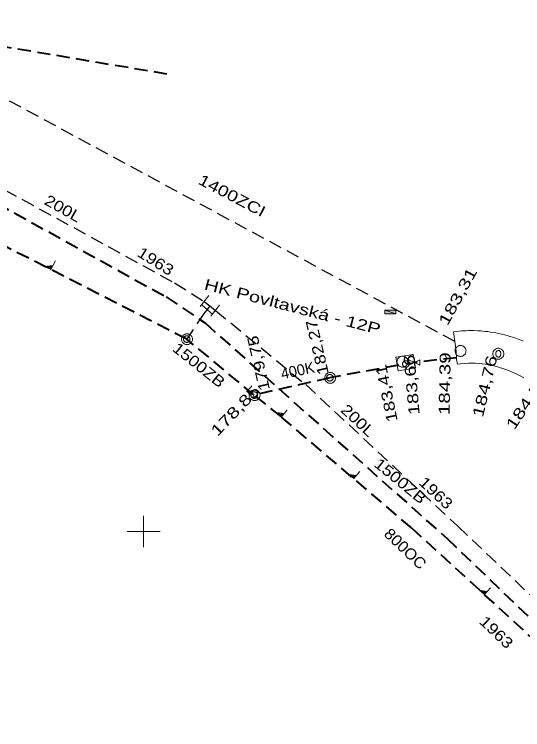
# Model space of a CAD drawing. Extents: x -740851 to -738888, y -1041382 to -1040235.
# Drawn here: x -739761.8 to -739715.4, y -1040568.1 to -1040502.8 of the extents above; entities that cross this region are included whole.
import ezdxf

# ---------------------------------------------------------------- set-up
doc = ezdxf.new("R2010")
doc.units = 0
doc.header["$LTSCALE"] = 0.4
doc.linetypes.add('MEDIUM_DASHED', pattern=[4.5, 3, -1.5])
for name, color, linetype, lineweight in [('1', 7, 'Continuous', 13), ('18', 7, 'Continuous', 13), ('20', 7, 'MEDIUM_DASHED', 25), ('8', 7, 'Continuous', 13)]:
    doc.layers.add(name, color=color, linetype=linetype, lineweight=lineweight)

msp = doc.modelspace()

# ---------------------------------------------------------------- hatches: boundary and pattern name
at = {"layer": '18'}
msp.add_hatch(color=256, dxfattribs=at).paths.add_polyline_path([(-739727.98, -1040529.82), (-739727.98, -1040530.16), (-739726.98, -1040530.16), (-739726.98, -1040529.82)])

# ---------------------------------------------------------------- linework, layer by layer
at = {"layer": '1'}
for p, q in [((-739750, -1040548.571), (-739750, -1040551.429)), ((-739751.48, -1040550), (-739748.48, -1040550))]:
    msp.add_line(p, q, dxfattribs=at)
at = {"layer": '18', "linetype": 'MEDIUM_DASHED', "lineweight": 40}
for p, q in [((-739746.06, -1040532.45), (-739799.87, -1040504.96)), ((-739739.89, -1040537.56), (-739746.06, -1040532.45)), ((-739721.427, -1040534.154), (-739725.27, -1040534.59)), ((-739726.71, -1040534.83), (-739732.99, -1040535.98)), ((-739732.99, -1040535.98), (-739739.89, -1040537.56))]:
    msp.add_line(p, q, dxfattribs=at)
at = {"layer": '18', "linetype": 'MEDIUM_DASHED', "lineweight": 25}
msp.add_line((-739721.586, -1040532.672), (-739764.8, -1040509.34), dxfattribs=at)
at = {"layer": '18'}
for p, q in [((-739727.98, -1040529.82), (-739726.98, -1040530.16)), ((-739725.27, -1040534.59), (-739725.27, -1040534.26)), ((-739725.27, -1040534.59), (-739725.27, -1040534.87))]:
    msp.add_line(p, q, dxfattribs=at)
for points in [[(-739758.045, -1040525.295), (-739758.462, -1040526.112), (-739759.045, -1040525.814), (-739758.274, -1040525.743)], [(-739758.358, -1040525.803), (-739758.48, -1040526.041), (-739758.852, -1040525.851), (-739758.354, -1040525.805)], [(-739758.445, -1040525.867), (-739758.506, -1040525.986), (-739758.697, -1040525.889), (-739758.441, -1040525.869)], [(-739715.285, -1040535.999), (-739715.498, -1040535.875), (-739715.748, -1040535.737), (-739715.932, -1040535.643), (-739716.251, -1040535.491), (-739716.649, -1040535.321), (-739717.184, -1040535.126), (-739717.9, -1040534.921), (-739718.298, -1040534.833), (-739718.809, -1040534.746), (-739719.084, -1040534.712), (-739719.344, -1040534.687), (-739719.721, -1040534.664), (-739720.34, -1040534.658), (-739720.728, -1040534.676), (-739721.074, -1040534.706), (-739721.326, -1040534.735), (-739721.414, -1040534.316), (-739721.473, -1040533.565), (-739721.698, -1040531.779), (-739721.404, -1040531.744), (-739721.17, -1040531.721), (-739720.972, -1040531.706), (-739720.749, -1040531.692), (-739720.551, -1040531.683), (-739720.33, -1040531.677), (-739720.12, -1040531.676), (-739719.857, -1040531.678), (-739719.512, -1040531.69), (-739719.428, -1040531.694), (-739719.22, -1040531.707), (-739719.041, -1040531.722), (-739718.772, -1040531.748), (-739718.563, -1040531.773), (-739718.324, -1040531.805), (-739718.056, -1040531.848), (-739717.844, -1040531.885), (-739717.59, -1040531.936), (-739717.32, -1040531.995), (-739717.187, -1040532.027), (-739717.044, -1040532.063), (-739716.794, -1040532.13), (-739716.549, -1040532.201), (-739716.415, -1040532.243), (-739716, -1040532.381), (-739715.564, -1040532.545), (-739715.354, -1040532.631)], [(-739736.875, -1040538.899), (-739737.419, -1040539.537), (-739737.875, -1040539.149), (-739737.174, -1040539.249)], [(-739737.262, -1040539.285), (-739737.42, -1040539.471), (-739737.711, -1040539.223), (-739737.259, -1040539.287)], [(-739737.352, -1040539.323), (-739737.432, -1040539.416), (-739737.581, -1040539.289), (-739737.349, -1040539.326)], [(-739730.249, -1040544.549), (-739730.793, -1040545.187), (-739731.249, -1040544.799), (-739730.547, -1040544.899)], [(-739730.635, -1040544.935), (-739730.794, -1040545.12), (-739731.085, -1040544.872), (-739730.632, -1040544.937)], [(-739730.726, -1040544.973), (-739730.805, -1040545.066), (-739730.955, -1040544.939), (-739730.723, -1040544.976)], [(-739718.317, -1040555.147), (-739718.879, -1040555.761), (-739719.317, -1040555.36), (-739718.626, -1040555.484)], [(-739718.714, -1040555.516), (-739718.878, -1040555.695), (-739719.158, -1040555.439), (-739718.711, -1040555.519)], [(-739718.806, -1040555.551), (-739718.887, -1040555.641), (-739719.031, -1040555.509), (-739718.803, -1040555.554)]]:
    msp.add_lwpolyline(points, dxfattribs=at)
for points in [[(-739727.98, -1040529.82), (-739727.98, -1040530.16), (-739726.98, -1040530.16), (-739726.98, -1040529.82)], [(-739745.53, -1040532.46), (-739745.54, -1040532.41), (-739745.54, -1040532.36), (-739745.56, -1040532.31), (-739745.58, -1040532.26), (-739745.6, -1040532.21), (-739745.63, -1040532.17), (-739745.66, -1040532.13), (-739745.7, -1040532.09), (-739745.74, -1040532.06), (-739745.78, -1040532.03), (-739745.83, -1040532.01), (-739745.88, -1040531.99), (-739745.93, -1040531.97), (-739745.98, -1040531.97), (-739746.03, -1040531.96), (-739746.08, -1040531.97), (-739746.13, -1040531.97), (-739746.18, -1040531.99), (-739746.23, -1040532.01), (-739746.28, -1040532.03), (-739746.32, -1040532.06), (-739746.36, -1040532.09), (-739746.4, -1040532.13), (-739746.43, -1040532.17), (-739746.46, -1040532.21), (-739746.48, -1040532.26), (-739746.5, -1040532.31), (-739746.52, -1040532.36), (-739746.52, -1040532.41), (-739746.53, -1040532.46), (-739746.52, -1040532.51), (-739746.52, -1040532.56), (-739746.5, -1040532.61), (-739746.48, -1040532.66), (-739746.46, -1040532.71), (-739746.43, -1040532.75), (-739746.4, -1040532.79), (-739746.36, -1040532.83), (-739746.32, -1040532.86), (-739746.28, -1040532.89), (-739746.23, -1040532.91), (-739746.18, -1040532.93), (-739746.13, -1040532.95), (-739746.08, -1040532.95), (-739746.03, -1040532.96), (-739745.98, -1040532.95), (-739745.93, -1040532.95), (-739745.88, -1040532.93), (-739745.83, -1040532.91), (-739745.78, -1040532.89), (-739745.74, -1040532.86), (-739745.7, -1040532.83), (-739745.66, -1040532.79), (-739745.63, -1040532.75), (-739745.6, -1040532.71), (-739745.58, -1040532.66), (-739745.56, -1040532.61), (-739745.54, -1040532.56), (-739745.54, -1040532.51)], [(-739745.76, -1040532.45), (-739745.76, -1040532.42), (-739745.766, -1040532.39), (-739745.772, -1040532.36), (-739745.784, -1040532.33), (-739745.802, -1040532.3), (-739745.82, -1040532.276), (-739745.838, -1040532.252), (-739745.862, -1040532.228), (-739745.886, -1040532.21), (-739745.91, -1040532.192), (-739745.94, -1040532.174), (-739745.97, -1040532.162), (-739746, -1040532.156), (-739746.03, -1040532.15), (-739746.06, -1040532.15), (-739746.09, -1040532.15), (-739746.12, -1040532.156), (-739746.15, -1040532.162), (-739746.18, -1040532.174), (-739746.21, -1040532.192), (-739746.234, -1040532.21), (-739746.258, -1040532.228), (-739746.282, -1040532.252), (-739746.3, -1040532.276), (-739746.318, -1040532.3), (-739746.336, -1040532.33), (-739746.348, -1040532.36), (-739746.354, -1040532.39), (-739746.36, -1040532.42), (-739746.36, -1040532.45), (-739746.36, -1040532.48), (-739746.354, -1040532.51), (-739746.348, -1040532.54), (-739746.336, -1040532.57), (-739746.318, -1040532.6), (-739746.3, -1040532.624), (-739746.282, -1040532.648), (-739746.258, -1040532.672), (-739746.234, -1040532.69), (-739746.21, -1040532.708), (-739746.18, -1040532.726), (-739746.15, -1040532.738), (-739746.12, -1040532.744), (-739746.09, -1040532.75), (-739746.06, -1040532.75), (-739746.03, -1040532.75), (-739746, -1040532.744), (-739745.97, -1040532.738), (-739745.94, -1040532.726), (-739745.91, -1040532.708), (-739745.886, -1040532.69), (-739745.862, -1040532.672), (-739745.838, -1040532.648), (-739745.82, -1040532.624), (-739745.802, -1040532.6), (-739745.784, -1040532.57), (-739745.772, -1040532.54), (-739745.766, -1040532.51), (-739745.76, -1040532.48)], [(-739720.617, -1040533.774), (-739720.601, -1040533.725), (-739720.577, -1040533.681), (-739720.571, -1040533.628), (-739720.564, -1040533.574), (-739720.558, -1040533.52), (-739720.565, -1040533.47), (-739720.572, -1040533.421), (-739720.588, -1040533.366), (-739720.609, -1040533.32), (-739720.629, -1040533.274), (-739720.664, -1040533.233), (-739720.698, -1040533.191), (-739720.733, -1040533.149), (-739720.777, -1040533.125), (-739720.816, -1040533.092), (-739720.865, -1040533.077), (-739720.909, -1040533.052), (-739720.963, -1040533.046), (-739721.017, -1040533.039), (-739721.07, -1040533.033), (-739721.12, -1040533.04), (-739721.17, -1040533.047), (-739721.225, -1040533.063), (-739721.27, -1040533.084), (-739721.316, -1040533.105), (-739721.358, -1040533.139), (-739721.4, -1040533.174), (-739721.442, -1040533.208), (-739721.466, -1040533.252), (-739721.499, -1040533.291), (-739721.514, -1040533.34), (-739721.538, -1040533.384), (-739721.545, -1040533.438), (-739721.551, -1040533.492), (-739721.558, -1040533.546), (-739721.551, -1040533.595), (-739721.543, -1040533.645), (-739721.527, -1040533.7), (-739721.507, -1040533.746), (-739721.486, -1040533.791), (-739721.451, -1040533.833), (-739721.417, -1040533.875), (-739721.383, -1040533.917), (-739721.338, -1040533.941), (-739721.299, -1040533.974), (-739721.25, -1040533.989), (-739721.206, -1040534.013), (-739721.152, -1040534.02), (-739721.099, -1040534.026), (-739721.045, -1040534.033), (-739720.995, -1040534.026), (-739720.945, -1040534.019), (-739720.891, -1040534.003), (-739720.845, -1040533.982), (-739720.799, -1040533.961), (-739720.757, -1040533.927), (-739720.716, -1040533.892), (-739720.674, -1040533.858), (-739720.65, -1040533.814)], [(-739726.97, -1040534.11), (-739725.38, -1040533.85), (-739725.17, -1040535.07), (-739726.76, -1040535.34)], [(-739717.107, -1040533.795), (-739717.107, -1040533.745), (-739717.117, -1040533.695), (-739717.127, -1040533.645), (-739717.147, -1040533.595), (-739717.177, -1040533.545), (-739717.207, -1040533.505), (-739717.237, -1040533.465), (-739717.277, -1040533.425), (-739717.317, -1040533.395), (-739717.357, -1040533.365), (-739717.407, -1040533.335), (-739717.457, -1040533.315), (-739717.507, -1040533.305), (-739717.557, -1040533.295), (-739717.607, -1040533.295), (-739717.657, -1040533.295), (-739717.707, -1040533.305), (-739717.757, -1040533.315), (-739717.807, -1040533.335), (-739717.857, -1040533.365), (-739717.897, -1040533.395), (-739717.937, -1040533.425), (-739717.977, -1040533.465), (-739718.007, -1040533.505), (-739718.037, -1040533.545), (-739718.067, -1040533.595), (-739718.087, -1040533.645), (-739718.097, -1040533.695), (-739718.107, -1040533.745), (-739718.107, -1040533.795), (-739718.107, -1040533.845), (-739718.097, -1040533.895), (-739718.087, -1040533.945), (-739718.067, -1040533.995), (-739718.037, -1040534.045), (-739718.007, -1040534.085), (-739717.977, -1040534.125), (-739717.937, -1040534.165), (-739717.897, -1040534.195), (-739717.857, -1040534.225), (-739717.807, -1040534.255), (-739717.757, -1040534.275), (-739717.707, -1040534.285), (-739717.657, -1040534.295), (-739717.607, -1040534.295), (-739717.557, -1040534.295), (-739717.507, -1040534.285), (-739717.457, -1040534.275), (-739717.407, -1040534.255), (-739717.357, -1040534.225), (-739717.317, -1040534.195), (-739717.277, -1040534.165), (-739717.237, -1040534.125), (-739717.207, -1040534.085), (-739717.177, -1040534.045), (-739717.147, -1040533.995), (-739717.127, -1040533.945), (-739717.117, -1040533.895), (-739717.107, -1040533.845)], [(-739717.667, -1040533.485), (-739717.727, -1040533.515), (-739717.787, -1040533.575), (-739717.817, -1040533.625), (-739717.847, -1040533.715), (-739717.847, -1040533.875), (-739717.817, -1040533.965), (-739717.787, -1040534.015), (-739717.727, -1040534.075), (-739717.667, -1040534.105), (-739717.547, -1040534.105), (-739717.487, -1040534.075), (-739717.427, -1040534.015), (-739717.397, -1040533.965), (-739717.367, -1040533.875), (-739717.367, -1040533.715), (-739717.397, -1040533.625), (-739717.427, -1040533.575), (-739717.487, -1040533.515), (-739717.547, -1040533.485)], [(-739725.86, -1040534.51), (-739725.87, -1040534.46), (-739725.87, -1040534.41), (-739725.89, -1040534.36), (-739725.91, -1040534.31), (-739725.93, -1040534.26), (-739725.96, -1040534.22), (-739725.99, -1040534.18), (-739726.03, -1040534.14), (-739726.07, -1040534.11), (-739726.11, -1040534.08), (-739726.16, -1040534.06), (-739726.21, -1040534.04), (-739726.26, -1040534.02), (-739726.31, -1040534.02), (-739726.36, -1040534.01), (-739726.41, -1040534.02), (-739726.46, -1040534.02), (-739726.51, -1040534.04), (-739726.56, -1040534.06), (-739726.61, -1040534.08), (-739726.65, -1040534.11), (-739726.69, -1040534.14), (-739726.73, -1040534.18), (-739726.76, -1040534.22), (-739726.79, -1040534.26), (-739726.81, -1040534.31), (-739726.83, -1040534.36), (-739726.85, -1040534.41), (-739726.85, -1040534.46), (-739726.86, -1040534.51), (-739726.85, -1040534.56), (-739726.85, -1040534.61), (-739726.83, -1040534.66), (-739726.81, -1040534.71), (-739726.79, -1040534.76), (-739726.76, -1040534.8), (-739726.73, -1040534.84), (-739726.69, -1040534.88), (-739726.65, -1040534.91), (-739726.61, -1040534.94), (-739726.56, -1040534.96), (-739726.51, -1040534.98), (-739726.46, -1040535), (-739726.41, -1040535), (-739726.36, -1040535.01), (-739726.31, -1040535), (-739726.26, -1040535), (-739726.21, -1040534.98), (-739726.16, -1040534.96), (-739726.11, -1040534.94), (-739726.07, -1040534.91), (-739726.03, -1040534.88), (-739725.99, -1040534.84), (-739725.96, -1040534.8), (-739725.93, -1040534.76), (-739725.91, -1040534.71), (-739725.89, -1040534.66), (-739725.87, -1040534.61), (-739725.87, -1040534.56)], [(-739725.754, -1040534.721), (-739725.754, -1040534.691), (-739725.76, -1040534.661), (-739725.766, -1040534.631), (-739725.778, -1040534.601), (-739725.796, -1040534.571), (-739725.814, -1040534.547), (-739725.832, -1040534.523), (-739725.856, -1040534.499), (-739725.88, -1040534.481), (-739725.904, -1040534.463), (-739725.934, -1040534.445), (-739725.964, -1040534.433), (-739725.994, -1040534.427), (-739726.024, -1040534.421), (-739726.054, -1040534.421), (-739726.084, -1040534.421), (-739726.114, -1040534.427), (-739726.144, -1040534.433), (-739726.174, -1040534.445), (-739726.204, -1040534.463), (-739726.228, -1040534.481), (-739726.252, -1040534.499), (-739726.276, -1040534.523), (-739726.294, -1040534.547), (-739726.312, -1040534.571), (-739726.33, -1040534.601), (-739726.342, -1040534.631), (-739726.348, -1040534.661), (-739726.354, -1040534.691), (-739726.354, -1040534.721), (-739726.354, -1040534.751), (-739726.348, -1040534.781), (-739726.342, -1040534.811), (-739726.33, -1040534.841), (-739726.312, -1040534.871), (-739726.294, -1040534.895), (-739726.276, -1040534.919), (-739726.252, -1040534.943), (-739726.228, -1040534.961), (-739726.204, -1040534.979), (-739726.174, -1040534.997), (-739726.144, -1040535.009), (-739726.114, -1040535.015), (-739726.084, -1040535.021), (-739726.054, -1040535.021), (-739726.024, -1040535.021), (-739725.994, -1040535.015), (-739725.964, -1040535.009), (-739725.934, -1040534.997), (-739725.904, -1040534.979), (-739725.88, -1040534.961), (-739725.856, -1040534.943), (-739725.832, -1040534.919), (-739725.814, -1040534.895), (-739725.796, -1040534.871), (-739725.778, -1040534.841), (-739725.766, -1040534.811), (-739725.76, -1040534.781), (-739725.754, -1040534.751)], [(-739725.77, -1040534.34), (-739724.77, -1040534.84), (-739724.77, -1040534.34), (-739725.77, -1040534.84)], [(-739732.46, -1040535.99), (-739732.47, -1040535.94), (-739732.47, -1040535.89), (-739732.49, -1040535.84), (-739732.51, -1040535.79), (-739732.53, -1040535.74), (-739732.56, -1040535.7), (-739732.59, -1040535.66), (-739732.63, -1040535.62), (-739732.67, -1040535.59), (-739732.71, -1040535.56), (-739732.76, -1040535.54), (-739732.81, -1040535.52), (-739732.86, -1040535.5), (-739732.91, -1040535.5), (-739732.96, -1040535.49), (-739733.01, -1040535.5), (-739733.06, -1040535.5), (-739733.11, -1040535.52), (-739733.16, -1040535.54), (-739733.21, -1040535.56), (-739733.25, -1040535.59), (-739733.29, -1040535.62), (-739733.33, -1040535.66), (-739733.36, -1040535.7), (-739733.39, -1040535.74), (-739733.41, -1040535.79), (-739733.43, -1040535.84), (-739733.45, -1040535.89), (-739733.45, -1040535.94), (-739733.46, -1040535.99), (-739733.45, -1040536.04), (-739733.45, -1040536.09), (-739733.43, -1040536.14), (-739733.41, -1040536.19), (-739733.39, -1040536.24), (-739733.36, -1040536.28), (-739733.33, -1040536.32), (-739733.29, -1040536.36), (-739733.25, -1040536.39), (-739733.21, -1040536.42), (-739733.16, -1040536.44), (-739733.11, -1040536.46), (-739733.06, -1040536.48), (-739733.01, -1040536.48), (-739732.96, -1040536.49), (-739732.91, -1040536.48), (-739732.86, -1040536.48), (-739732.81, -1040536.46), (-739732.76, -1040536.44), (-739732.71, -1040536.42), (-739732.67, -1040536.39), (-739732.63, -1040536.36), (-739732.59, -1040536.32), (-739732.56, -1040536.28), (-739732.53, -1040536.24), (-739732.51, -1040536.19), (-739732.49, -1040536.14), (-739732.47, -1040536.09), (-739732.47, -1040536.04)], [(-739732.69, -1040535.98), (-739732.69, -1040535.95), (-739732.696, -1040535.92), (-739732.702, -1040535.89), (-739732.714, -1040535.86), (-739732.732, -1040535.83), (-739732.75, -1040535.806), (-739732.768, -1040535.782), (-739732.792, -1040535.758), (-739732.816, -1040535.74), (-739732.84, -1040535.722), (-739732.87, -1040535.704), (-739732.9, -1040535.692), (-739732.93, -1040535.686), (-739732.96, -1040535.68), (-739732.99, -1040535.68), (-739733.02, -1040535.68), (-739733.05, -1040535.686), (-739733.08, -1040535.692), (-739733.11, -1040535.704), (-739733.14, -1040535.722), (-739733.164, -1040535.74), (-739733.188, -1040535.758), (-739733.212, -1040535.782), (-739733.23, -1040535.806), (-739733.248, -1040535.83), (-739733.266, -1040535.86), (-739733.278, -1040535.89), (-739733.284, -1040535.92), (-739733.29, -1040535.95), (-739733.29, -1040535.98), (-739733.29, -1040536.01), (-739733.284, -1040536.04), (-739733.278, -1040536.07), (-739733.266, -1040536.1), (-739733.248, -1040536.13), (-739733.23, -1040536.154), (-739733.212, -1040536.178), (-739733.188, -1040536.202), (-739733.164, -1040536.22), (-739733.14, -1040536.238), (-739733.11, -1040536.256), (-739733.08, -1040536.268), (-739733.05, -1040536.274), (-739733.02, -1040536.28), (-739732.99, -1040536.28), (-739732.96, -1040536.28), (-739732.93, -1040536.274), (-739732.9, -1040536.268), (-739732.87, -1040536.256), (-739732.84, -1040536.238), (-739732.816, -1040536.22), (-739732.792, -1040536.202), (-739732.768, -1040536.178), (-739732.75, -1040536.154), (-739732.732, -1040536.13), (-739732.714, -1040536.1), (-739732.702, -1040536.07), (-739732.696, -1040536.04), (-739732.69, -1040536.01)], [(-739739.36, -1040537.57), (-739739.37, -1040537.52), (-739739.37, -1040537.47), (-739739.39, -1040537.42), (-739739.41, -1040537.37), (-739739.43, -1040537.32), (-739739.46, -1040537.28), (-739739.49, -1040537.24), (-739739.53, -1040537.2), (-739739.57, -1040537.17), (-739739.61, -1040537.14), (-739739.66, -1040537.12), (-739739.71, -1040537.1), (-739739.76, -1040537.08), (-739739.81, -1040537.08), (-739739.86, -1040537.07), (-739739.91, -1040537.08), (-739739.96, -1040537.08), (-739740.01, -1040537.1), (-739740.06, -1040537.12), (-739740.11, -1040537.14), (-739740.15, -1040537.17), (-739740.19, -1040537.2), (-739740.23, -1040537.24), (-739740.26, -1040537.28), (-739740.29, -1040537.32), (-739740.31, -1040537.37), (-739740.33, -1040537.42), (-739740.35, -1040537.47), (-739740.35, -1040537.52), (-739740.36, -1040537.57), (-739740.35, -1040537.62), (-739740.35, -1040537.67), (-739740.33, -1040537.72), (-739740.31, -1040537.77), (-739740.29, -1040537.82), (-739740.26, -1040537.86), (-739740.23, -1040537.9), (-739740.19, -1040537.94), (-739740.15, -1040537.97), (-739740.11, -1040538), (-739740.06, -1040538.02), (-739740.01, -1040538.04), (-739739.96, -1040538.06), (-739739.91, -1040538.06), (-739739.86, -1040538.07), (-739739.81, -1040538.06), (-739739.76, -1040538.06), (-739739.71, -1040538.04), (-739739.66, -1040538.02), (-739739.61, -1040538), (-739739.57, -1040537.97), (-739739.53, -1040537.94), (-739739.49, -1040537.9), (-739739.46, -1040537.86), (-739739.43, -1040537.82), (-739739.41, -1040537.77), (-739739.39, -1040537.72), (-739739.37, -1040537.67), (-739739.37, -1040537.62)], [(-739739.59, -1040537.56), (-739739.59, -1040537.53), (-739739.596, -1040537.5), (-739739.602, -1040537.47), (-739739.614, -1040537.44), (-739739.632, -1040537.41), (-739739.65, -1040537.386), (-739739.668, -1040537.362), (-739739.692, -1040537.338), (-739739.716, -1040537.32), (-739739.74, -1040537.302), (-739739.77, -1040537.284), (-739739.8, -1040537.272), (-739739.83, -1040537.266), (-739739.86, -1040537.26), (-739739.89, -1040537.26), (-739739.92, -1040537.26), (-739739.95, -1040537.266), (-739739.98, -1040537.272), (-739740.01, -1040537.284), (-739740.04, -1040537.302), (-739740.064, -1040537.32), (-739740.088, -1040537.338), (-739740.112, -1040537.362), (-739740.13, -1040537.386), (-739740.148, -1040537.41), (-739740.166, -1040537.44), (-739740.178, -1040537.47), (-739740.184, -1040537.5), (-739740.19, -1040537.53), (-739740.19, -1040537.56), (-739740.19, -1040537.59), (-739740.184, -1040537.62), (-739740.178, -1040537.65), (-739740.166, -1040537.68), (-739740.148, -1040537.71), (-739740.13, -1040537.734), (-739740.112, -1040537.758), (-739740.088, -1040537.782), (-739740.064, -1040537.8), (-739740.04, -1040537.818), (-739740.01, -1040537.836), (-739739.98, -1040537.848), (-739739.95, -1040537.854), (-739739.92, -1040537.86), (-739739.89, -1040537.86), (-739739.86, -1040537.86), (-739739.83, -1040537.854), (-739739.8, -1040537.848), (-739739.77, -1040537.836), (-739739.74, -1040537.818), (-739739.716, -1040537.8), (-739739.692, -1040537.782), (-739739.668, -1040537.758), (-739739.65, -1040537.734), (-739739.632, -1040537.71), (-739739.614, -1040537.68), (-739739.602, -1040537.65), (-739739.596, -1040537.62), (-739739.59, -1040537.59)]]:
    msp.add_lwpolyline(points, close=True, dxfattribs=at)
at = {"layer": '18', "linetype": 'MEDIUM_DASHED', "lineweight": 40}
msp.add_lwpolyline([(-739713.989, -1040560.24), (-739725.522, -1040549.684), (-739737.438, -1040539.524), (-739739.89, -1040537.56)], dxfattribs=at)
at = {"layer": '20', "lineweight": 40}
msp.add_line((-739747.86, -1040508.27), (-739780.43, -1040502.81), dxfattribs=at)
at = {"layer": '8'}
for p, q in [((-739744.027, -1040528.469), (-739744.829, -1040529.469)), ((-739743.66, -1040530.199), (-739744.66, -1040529.367)), ((-739743.86, -1040530.37), (-739743.064, -1040529.37))]:
    msp.add_line(p, q, dxfattribs=at)
at = {"layer": '8', "lineweight": 25}
msp.add_line((-739743.94, -1040529.424), (-739744.2, -1040529.75), dxfattribs=at)
at = {"layer": '8', "linetype": 'MEDIUM_DASHED', "lineweight": 40}
msp.add_lwpolyline([(-739800.406, -1040510.509), (-739783.874, -1040510.33), (-739769.682, -1040516.575), (-739747.937, -1040528.604), (-739744.345, -1040531.012), (-739722.292, -1040550.654), (-739710.435, -1040562.012), (-739703.68, -1040568.1)], dxfattribs=at)
at = {"layer": '8', "linetype": 'MEDIUM_DASHED', "lineweight": 25}
for points in [[(-739765.844, -1040517.089), (-739747.16, -1040527.33), (-739744.46, -1040529.01)], [(-739744.46, -1040529.01), (-739743.94, -1040529.424), (-739743.43, -1040529.83)], [(-739744.2, -1040529.75), (-739744.468, -1040530.073), (-739746.06, -1040532.45)], [(-739743.43, -1040529.83), (-739735.19, -1040536.61), (-739721.3, -1040549.54), (-739710.4, -1040559.88)]]:
    msp.add_lwpolyline(points, dxfattribs=at)

# ---------------------------------------------------------------- texts
at = {"layer": '18'}
for s, rotation, width, p in [('1400ZCI', 332.293, 1.3, (-739745.094, -1040518.243)), ('183,31', 61.262, 1.4, (-739722.251, -1040531.304)), ('HK Povltavská - 12P', 345.467, 1.35, (-739744.532, -1040527.897)), ('182,27', 103.083, 1.25, (-739733.079, -1040535.576)), ('179,75', 102.846, 1.25, (-739738.452, -1040537.042)), ('1500ZB', 321.368, 1.2, (-739747.451, -1040533.454)), ('184,39', 88.955, 1.4, (-739722.059, -1040539.394)), ('183,66', 95.078, 1.35, (-739724.787, -1040539.33)), ('184,76', 76.462, 1.4, (-739719.026, -1040539.655)), ('183,41', 101.649, 1.3, (-739726.788, -1040539.911)), ('184,51', 56.105, 1.4, (-739716.153, -1040540.811)), ('178,85', 46.431, 1.4, (-739743.248, -1040541.399)), ('1500ZB', 320.548, 1.2, (-739729.043, -1040543.995))]:
    msp.add_text(s, height=1, rotation=rotation, dxfattribs=dict(at, width=width)).set_placement(p)
msp.add_text('400K', height=1, rotation=11.999, dxfattribs=at).set_placement((-739737.354, -1040536.127))
at = {"layer": '8'}
for s, rotation, width, p in [('200L', 330.623, 1.2, (-739759.151, -1040520.095)), ('1963', 328.11, 1.2, (-739750.67, -1040524.825)), ('200L', 317.049, 1.2, (-739732.078, -1040539.023)), ('1963', 317.05, 1.2, (-739724.951, -1040545.638)), ('800OC', 316.231, 1.1, (-739728.131, -1040550.329)), ('1963', 316.231, 1.2, (-739719.42, -1040558.327))]:
    msp.add_text(s, height=1, rotation=rotation, dxfattribs=dict(at, width=width)).set_placement(p)

doc.saveas('drawing.dxf')
